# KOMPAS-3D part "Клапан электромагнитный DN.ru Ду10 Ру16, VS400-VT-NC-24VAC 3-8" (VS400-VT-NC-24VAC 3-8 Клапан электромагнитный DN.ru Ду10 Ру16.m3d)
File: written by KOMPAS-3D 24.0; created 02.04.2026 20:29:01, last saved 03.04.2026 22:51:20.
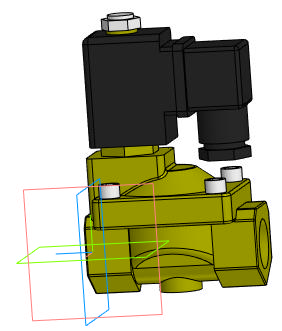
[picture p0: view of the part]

Document properties: Автор: artio; Полное имя файла: C:\Users\artio\OneDrive\Рабочий стол\Клапан электромагнитный DN.ru\VS400-VT-NC\VS400-VT-NC-24VAC 3-8 Клапан электромагнитный DN.ru Ду10 Ру16.m3d

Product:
- Body: Тело 1  | qty 1
    Масса: 1.030062
- Part/product: Клапан электромагнитный DN.ru Ду10 Ру16  | designation VS400-VT-NC-24VAC 3-8
    Масса: 0.797
    Раздел спецификации: Прочие изделия
    Примечание: D130-05632
    additional columns: ef56311e-7521-43dc-8291-0e6108b3d81d; VS400-ET-NC-220VAC 3-8; artio; c; Шероховатость не задана; Да

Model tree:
1. Операция без истории:1

Expressions: VS400-VT-NC-24VAC 3-8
